Omron CX-Programmer project NuevoProyecto (CX-Programmer 9.50)

# PLC NewPLC1: CP1L-E EM

## Program P7_5_1 (cyclic task 0)
Local symbols
Ab 100.01 BOOL
As 100.00 BOOL
B 100.02 BOOL
C 100.03 BOOL
Etapa_0 10.00 BOOL
Etapa_1 10.01 BOOL
Etapa_10 10.06 BOOL
Etapa_11 10.07 BOOL
Etapa_12 10.08 BOOL
Etapa_13 10.09 BOOL
Etapa_14 10.10 BOOL
Etapa_15 10.11 BOOL
Etapa_2 10.02 BOOL
Etapa_3 10.03 BOOL
Etapa_4 10.04 BOOL
Etapa_5 10.05 BOOL
a_0 0.01 BOOL
a_1 0.02 BOOL
a_2 0.03 BOOL
b_0 0.04 BOOL
b_1 0.05 BOOL
c_0 0.06 BOOL
c_1 0.07 BOOL
m 0.00 BOOL

### Section Sección1_GRAFCET_principal
; Etapas X0 ... X5

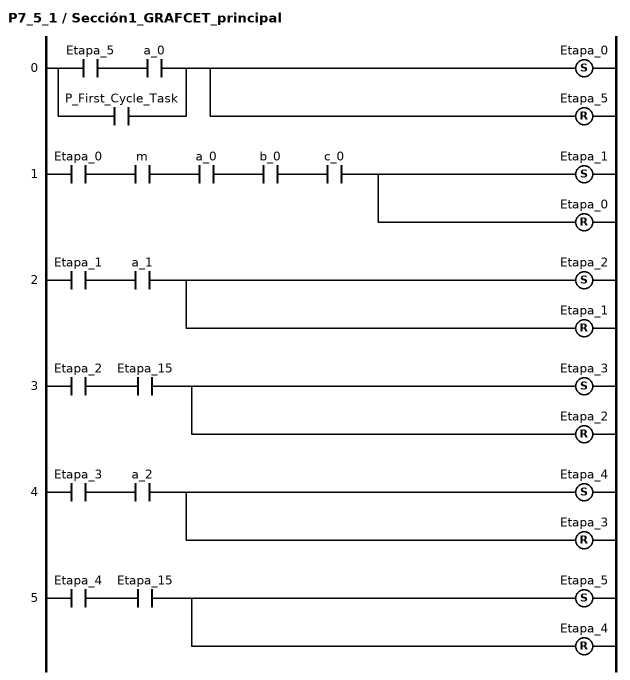
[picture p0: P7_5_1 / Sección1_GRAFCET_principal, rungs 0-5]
; rung 0
LD Etapa_5
AND a_0
OR P_First_Cycle_Task
SET Etapa_0
RSET Etapa_5
; rung 1
LD Etapa_0
AND m
AND a_0
AND b_0
AND c_0
SET Etapa_1
RSET Etapa_0
; rung 2
LD Etapa_1
AND a_1
SET Etapa_2
RSET Etapa_1
; rung 3
LD Etapa_2
AND Etapa_15
SET Etapa_3
RSET Etapa_2
; rung 4
LD Etapa_3
AND a_2
SET Etapa_4
RSET Etapa_3
; rung 5
LD Etapa_4
AND Etapa_15
SET Etapa_5
RSET Etapa_4

### Section Sección2_GRAFCET_auxiliar
; Etapas X10 ... X15

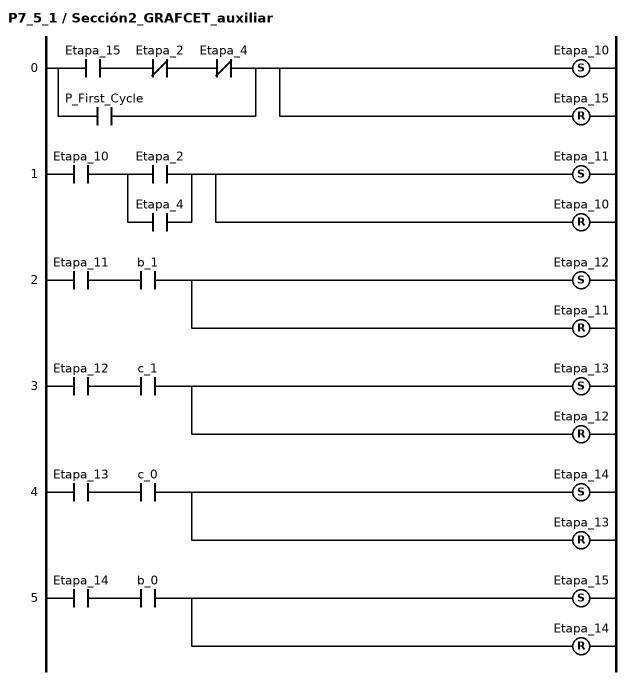
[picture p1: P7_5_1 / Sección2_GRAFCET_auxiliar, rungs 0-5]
; rung 0
LD Etapa_15
ANDNOT Etapa_2
ANDNOT Etapa_4
OR P_First_Cycle
SET Etapa_10
RSET Etapa_15
; rung 1
LD Etapa_10
LD Etapa_2
OR Etapa_4
ANDLD
SET Etapa_11
RSET Etapa_10
; rung 2
LD Etapa_11
AND b_1
SET Etapa_12
RSET Etapa_11
; rung 3
LD Etapa_12
AND c_1
SET Etapa_13
RSET Etapa_12
; rung 4
LD Etapa_13
AND c_0
SET Etapa_14
RSET Etapa_13
; rung 5
LD Etapa_14
AND b_0
SET Etapa_15
RSET Etapa_14

### Section Sección3_Salidas

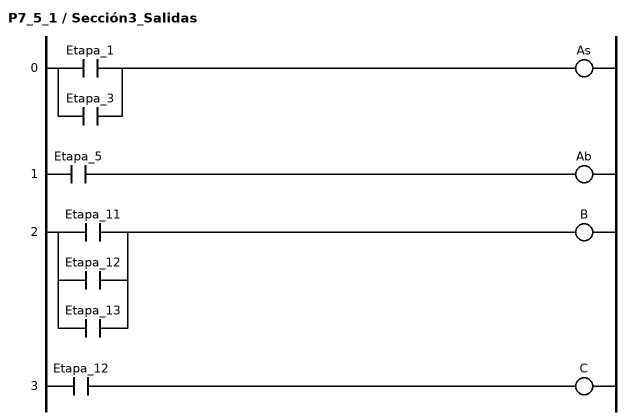
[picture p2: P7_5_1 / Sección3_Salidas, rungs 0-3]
; rung 0
LD Etapa_1
OR Etapa_3
OUT As
; rung 1
LD Etapa_5
OUT Ab
; rung 2
LD Etapa_11
OR Etapa_12
OR Etapa_13
OUT B
; rung 3
LD Etapa_12
OUT C

### Section Sección4_END
; rung 0: Fin de programa
END(001)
